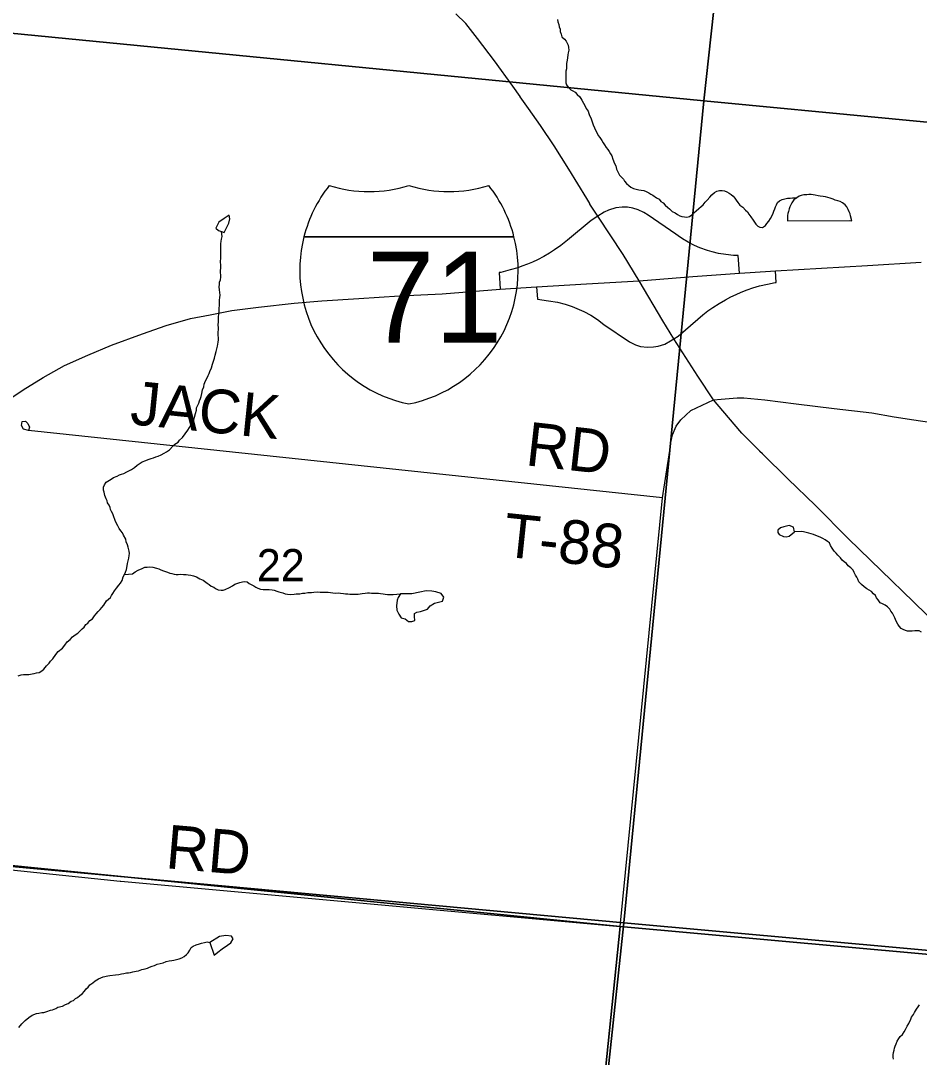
# Model space of a CAD drawing. Extents: x 0 to 1064, y 0 to 440.
# Drawn here: x 276.2 to 294.9, y 198.04 to 219.61 of the extents above; entities that cross this region are included whole.
import ezdxf

# ---------------------------------------------------------------- set-up
doc = ezdxf.new("R2010")
doc.units = 0
for name, color, linetype in [('GM_X_Interchange_Ramps', 7, 'Continuous'), ('GM_X_Interstate_Location', 7, 'Continuous'), ('GM_X_Interstate_Route', 7, 'Continuous'), ('GM_X_Interstate_Shield', 7, 'Continuous'), ('GM_X_Minor_Lake', 7, 'Continuous'), ('GM_X_Minor_River', 7, 'Continuous'), ('GM_X_Section', 7, 'Continuous'), ('GM_X_Section_Text', 7, 'Continuous'), ('GM_X_State_Route', 7, 'Continuous'), ('GM_X_Township', 7, 'Continuous'), ('GM_X_Township_Road', 7, 'Continuous'), ('GM_X_Township_Road_Text', 7, 'Continuous')]:
    doc.layers.add(name, color=color, linetype=linetype)

msp = doc.modelspace()

# ---------------------------------------------------------------- linework, layer by layer
at = {"layer": 'GM_X_Interchange_Ramps'}
for points in [[(291.163, 214.351), (291.137, 214.719), (291.036, 214.723), (290.875, 214.74), (290.728, 214.765), (290.593, 214.796), (290.496, 214.825), (290.338, 214.881), (290.222, 214.932), (290.094, 214.997), (289.979, 215.065), (289.884, 215.128), (289.835, 215.163), (289.263, 215.561), (289.171, 215.618), (289.055, 215.671), (288.939, 215.705), (288.83, 215.723), (288.721, 215.728), (288.59, 215.712), (288.433, 215.666), (288.342, 215.619), (288.214, 215.537)], [(288.214, 215.537), (288.077, 215.45), (287.582, 215.039), (287.446, 214.932), (287.311, 214.837), (287.21, 214.772), (287.088, 214.702), (286.955, 214.632), (286.853, 214.585), (286.752, 214.542), (286.632, 214.497), (286.545, 214.467), (286.387, 214.421), (286.197, 214.369), (286.16, 214.364), (286.183, 214.017)], [(289.792, 212.983), (289.883, 213.04), (290.295, 213.395), (290.399, 213.484), (290.505, 213.566), (290.61, 213.641), (290.739, 213.724), (290.871, 213.801), (290.981, 213.859), (291.09, 213.911), (291.196, 213.957), (291.322, 214.006), (291.44, 214.045), (291.579, 214.086), (291.745, 214.126), (291.904, 214.158), (291.925, 214.161), (291.91, 214.398)], [(286.939, 214.066), (286.956, 213.809), (287.188, 213.777), (287.377, 213.747), (287.533, 213.708), (287.676, 213.661), (287.92, 213.558), (288.065, 213.477), (288.204, 213.388), (288.341, 213.288), (288.87, 212.925), (288.997, 212.861), (289.101, 212.829), (289.247, 212.81), (289.371, 212.817), (289.467, 212.836), (289.608, 212.878), (289.729, 212.944), (289.792, 212.983)]]:
    msp.add_lwpolyline(points, dxfattribs=at)
at = {"layer": 'GM_X_Interstate_Route'}
msp.add_lwpolyline([(275.782, 211.603), (276.252, 211.926), (276.672, 212.184), (277.116, 212.429), (277.602, 212.649), (278.088, 212.856), (278.738, 213.09), (279.229, 213.261), (279.738, 213.407), (280.148, 213.489), (280.594, 213.576), (281.15, 213.642), (281.894, 213.728), (282.467, 213.776), (283.236, 213.825), (284.083, 213.878), (284.973, 213.924), (286.183, 214.017), (286.939, 214.066), (287.978, 214.128), (289.074, 214.193), (290.192, 214.283), (291.163, 214.351), (291.381, 214.364), (291.91, 214.398), (293.825, 214.514), (294.946, 214.579)], dxfattribs=at)
at = {"layer": 'GM_X_Interstate_Shield'}
for p, q in [((282.096, 215.11), (286.468, 215.11)), ((286.468, 215.11), (282.096, 215.11)), ((286.468, 215.11), (282.096, 215.11))]:
    msp.add_line(p, q, dxfattribs=at)
for centre, start, end in [((284.851, 214.414), 141.669, 165.8066), ((283.452, 218.893), 253.0091, 286.9909), ((285.113, 218.893), 253.0091, 286.9909), ((283.714, 214.414), 14.1934, 38.331), ((284.851, 214.414), 165.8066, 258.463), ((283.714, 214.414), 281.537, 14.1934)]:
    msp.add_arc(centre, 2.841, start, end, dxfattribs=at)
at = {"layer": 'GM_X_Minor_Lake'}
for points in [[(293.5, 215.445), (293.472, 215.543), (293.462, 215.585), (293.445, 215.628), (293.422, 215.678), (293.394, 215.733), (293.358, 215.777), (293.305, 215.815), (293.257, 215.841), (293.209, 215.86), (293.155, 215.874), (293.113, 215.894), (293.052, 215.914), (292.998, 215.928), (292.95, 215.941), (292.901, 215.949), (292.841, 215.957), (292.798, 215.964), (292.738, 215.978), (292.696, 215.986), (292.653, 215.987), (292.604, 215.988), (292.562, 215.984), (292.501, 215.985), (292.445, 215.969), (292.402, 215.952), (292.352, 215.917), (292.296, 215.876), (292.252, 215.817), (292.232, 215.775), (292.212, 215.733), (292.193, 215.691), (292.179, 215.637), (292.171, 215.595), (292.164, 215.553), (292.162, 215.498), (292.16, 215.443)], [(280.261, 215.29), (280.315, 215.241), (280.381, 215.221), (280.435, 215.201), (280.486, 215.297), (280.531, 215.393), (280.552, 215.484), (280.542, 215.563), (280.436, 215.493), (280.325, 215.411)], [(280.325, 215.411), (280.261, 215.29)], [(292.16, 215.443), (293.457, 215.446), (293.5, 215.445)], [(284.105, 207.68), (284.061, 207.602), (284.035, 207.547), (284.02, 207.432), (284.03, 207.341), (284.071, 207.255), (284.118, 207.181), (284.202, 207.16), (284.274, 207.104), (284.341, 207.102), (284.402, 207.125), (284.398, 207.21), (284.4, 207.271), (284.449, 207.3), (284.523, 207.311), (284.584, 207.333), (284.67, 207.362), (284.727, 207.433), (284.813, 207.486), (284.923, 207.514), (284.979, 207.531), (285.011, 207.609), (284.952, 207.69), (284.843, 207.723), (284.758, 207.737), (284.643, 207.746), (284.508, 207.718)], [(284.508, 207.718), (284.343, 207.68), (284.203, 207.677), (284.105, 207.68)], [(280.141, 200.428), (280.225, 200.158), (280.306, 200.223), (280.393, 200.294), (280.505, 200.371), (280.573, 200.418), (280.623, 200.502), (280.588, 200.557), (280.473, 200.572), (280.338, 200.551)], [(280.338, 200.551), (280.141, 200.428)]]:
    msp.add_lwpolyline(points, dxfattribs=at)
at = {"layer": 'GM_X_Minor_River'}
for points in [[(287.372, 219.629), (287.383, 219.58), (287.399, 219.525), (287.41, 219.482), (287.427, 219.433), (287.431, 219.384), (287.448, 219.329), (287.464, 219.274), (287.517, 219.224), (287.552, 219.18), (287.575, 219.137), (287.598, 219.094), (287.603, 219.051), (287.607, 218.99), (287.599, 218.936), (287.592, 218.894), (287.584, 218.833), (287.576, 218.785), (287.561, 218.713), (287.558, 218.603), (287.55, 218.555), (287.547, 218.47), (287.546, 218.428), (287.544, 218.373), (287.548, 218.312), (287.559, 218.269), (287.594, 218.226), (287.653, 218.169), (287.695, 218.15), (287.743, 218.118), (287.784, 218.074), (287.837, 218.024), (287.883, 217.95), (287.918, 217.888), (287.941, 217.845), (287.969, 217.777), (288.01, 217.721), (288.026, 217.678), (288.043, 217.635), (288.066, 217.586), (288.083, 217.543), (288.094, 217.5), (288.116, 217.439), (288.144, 217.377), (288.167, 217.328), (288.202, 217.266), (288.218, 217.217), (288.253, 217.173), (288.294, 217.111), (288.323, 217.068), (288.352, 217.024), (288.387, 216.969), (288.422, 216.925), (288.451, 216.882), (288.48, 216.838), (288.503, 216.795), (288.525, 216.728), (288.558, 216.636), (288.587, 216.586), (288.603, 216.519), (288.637, 216.451), (288.666, 216.395), (288.707, 216.352), (288.748, 216.308), (288.771, 216.265), (288.813, 216.221), (288.86, 216.177), (288.901, 216.145), (288.955, 216.113), (289.009, 216.099), (289.064, 216.086), (289.118, 216.078), (289.173, 216.07), (289.221, 216.05), (289.275, 216.024), (289.317, 215.999), (289.358, 215.973), (289.436, 215.922), (289.49, 215.89), (289.525, 215.847), (289.572, 215.815), (289.613, 215.765), (289.667, 215.721), (289.708, 215.689), (289.761, 215.639), (289.821, 215.607), (289.875, 215.575), (289.923, 215.549), (289.965, 215.53), (290.019, 215.522), (290.068, 215.52), (290.123, 215.531), (290.173, 215.566), (290.211, 215.607), (290.261, 215.648)], [(290.261, 215.648), (290.318, 215.701), (290.362, 215.742), (290.405, 215.777), (290.45, 215.83), (290.488, 215.872), (290.545, 215.937), (290.589, 215.984), (290.645, 216.031), (290.689, 216.06), (290.744, 216.07), (290.799, 216.074), (290.847, 216.067), (290.895, 216.047), (290.949, 216.021), (290.991, 215.99), (291.032, 215.958), (291.068, 215.914), (291.09, 215.871), (291.125, 215.822), (291.172, 215.765), (291.232, 215.727), (291.285, 215.665), (291.326, 215.627), (291.355, 215.578), (291.396, 215.522), (291.448, 215.459), (291.477, 215.416), (291.5, 215.373), (291.541, 215.329), (291.583, 215.31), (291.638, 215.302), (291.7, 215.342), (291.732, 215.384), (291.776, 215.437), (291.809, 215.491), (291.841, 215.55), (291.861, 215.598), (291.88, 215.64), (291.894, 215.695), (291.914, 215.736), (291.934, 215.778), (291.953, 215.82), (291.997, 215.855), (292.053, 215.884), (292.108, 215.9), (292.163, 215.911), (292.218, 215.915), (292.267, 215.92), (292.352, 215.917)], [(280.317, 213.223), (280.313, 213.272), (280.315, 213.344), (280.317, 213.399), (280.319, 213.454), (280.326, 213.496), (280.334, 213.568), (280.33, 213.623), (280.338, 213.678), (280.34, 213.738), (280.342, 213.793), (280.344, 213.847), (280.351, 213.896), (280.347, 213.951), (280.337, 214.005), (280.333, 214.066), (280.34, 214.115), (280.342, 214.169), (280.362, 214.217), (280.37, 214.272), (280.365, 214.32), (280.361, 214.363), (280.362, 214.411), (280.364, 214.46), (280.366, 214.509), (280.362, 214.594), (280.365, 214.666), (280.367, 214.739), (280.369, 214.8), (280.365, 214.855), (280.367, 214.909), (280.368, 214.964), (280.376, 215.018), (280.384, 215.061), (280.392, 215.115), (280.381, 215.221)], [(278.403, 208.188), (278.418, 208.26), (278.425, 208.309), (278.44, 208.369), (278.454, 208.423), (278.462, 208.478), (278.463, 208.52), (278.458, 208.569), (278.437, 208.648), (278.426, 208.697), (278.398, 208.765), (278.388, 208.82), (278.342, 208.9), (278.319, 208.949), (278.284, 208.993), (278.249, 209.043), (278.226, 209.098), (278.174, 209.185), (278.158, 209.228), (278.141, 209.283), (278.119, 209.344), (278.09, 209.394), (278.073, 209.437), (278.062, 209.48), (278.045, 209.523), (278.011, 209.572), (278, 209.615), (277.983, 209.658), (277.955, 209.726), (277.939, 209.793), (277.922, 209.836), (277.924, 209.897), (277.944, 209.951), (277.982, 210.004), (278.082, 210.068), (278.132, 210.103), (278.206, 210.131), (278.255, 210.154), (278.298, 210.17), (278.347, 210.181), (278.409, 210.216), (278.508, 210.267), (278.571, 210.308), (278.627, 210.355), (278.689, 210.401), (278.733, 210.43), (278.807, 210.452), (278.856, 210.475), (278.918, 210.497), (278.967, 210.508), (279.016, 210.531), (279.066, 210.547), (279.128, 210.576), (279.189, 210.604), (279.233, 210.633), (279.301, 210.68), (279.371, 210.751), (279.409, 210.792), (279.477, 210.838), (279.509, 210.88), (279.566, 210.933), (279.623, 211.01), (279.68, 211.087), (279.712, 211.141), (279.745, 211.2), (279.771, 211.242), (279.803, 211.296), (279.817, 211.356), (279.838, 211.434), (279.858, 211.501), (279.86, 211.549), (279.88, 211.591), (279.906, 211.651), (279.926, 211.699), (279.946, 211.747), (279.959, 211.789), (279.973, 211.849), (279.988, 211.928), (280.014, 211.988), (280.022, 212.042), (280.049, 212.114), (280.081, 212.174), (280.101, 212.222), (280.121, 212.263), (280.141, 212.305), (280.174, 212.383), (280.194, 212.456), (280.215, 212.522), (280.235, 212.582), (280.249, 212.648), (280.27, 212.72), (280.284, 212.781), (280.298, 212.835), (280.306, 212.877), (280.313, 212.919), (280.315, 212.968), (280.316, 213.01), (280.312, 213.065), (280.314, 213.126), (280.316, 213.18), (280.317, 213.223)], [(292.309, 208.969), (292.287, 209.067), (292.197, 209.105), (292.087, 209.077), (292.013, 209.055), (291.957, 209.002), (291.962, 208.959), (291.991, 208.916)], [(291.991, 208.916), (292.076, 208.871), (292.136, 208.864), (292.197, 208.88), (292.309, 208.969)], [(294.952, 206.881), (294.899, 206.913), (294.813, 206.91), (294.758, 206.906), (294.703, 206.901), (294.661, 206.903), (294.619, 206.916), (294.57, 206.936), (294.529, 206.961), (294.487, 207.005), (294.458, 207.048), (294.424, 207.11), (294.396, 207.178), (294.367, 207.233), (294.344, 207.277), (294.315, 207.32), (294.292, 207.363), (294.245, 207.413), (294.191, 207.445), (294.138, 207.471), (294.09, 207.491), (294.049, 207.553), (294.014, 207.596), (293.991, 207.646), (293.95, 207.683), (293.909, 207.727), (293.861, 207.759), (293.813, 207.785), (293.759, 207.823), (293.7, 207.873), (293.647, 207.93), (293.625, 207.985), (293.602, 208.028), (293.573, 208.072), (293.55, 208.127), (293.527, 208.17), (293.48, 208.22), (293.421, 208.264), (293.386, 208.308), (293.338, 208.346), (293.297, 208.384), (293.262, 208.427), (293.209, 208.483), (293.174, 208.527), (293.132, 208.565), (293.092, 208.627), (293.057, 208.689), (293.035, 208.738), (292.993, 208.769), (292.945, 208.801), (292.898, 208.833), (292.856, 208.853), (292.808, 208.872), (292.754, 208.892), (292.7, 208.918), (292.657, 208.932), (292.603, 208.945), (292.549, 208.959), (292.494, 208.967), (292.452, 208.974), (292.309, 208.969)], [(276.15, 205.975), (276.212, 205.997), (276.261, 206.002), (276.303, 206), (276.371, 206.004), (276.438, 206.014), (276.481, 206.025), (276.53, 206.036), (276.585, 206.046), (276.641, 206.075), (276.685, 206.116), (276.736, 206.181), (276.792, 206.234), (276.824, 206.282), (276.868, 206.329), (276.932, 206.418), (276.983, 206.483), (277.071, 206.553), (277.121, 206.612), (277.172, 206.684), (277.229, 206.731), (277.279, 206.784), (277.335, 206.824), (277.391, 206.865), (277.435, 206.906), (277.48, 206.954), (277.523, 206.989), (277.556, 207.042), (277.599, 207.071), (277.637, 207.125), (277.693, 207.159), (277.738, 207.225), (277.77, 207.266), (277.814, 207.314), (277.858, 207.355), (277.89, 207.396), (277.934, 207.443), (277.986, 207.533), (278.067, 207.603), (278.093, 207.645), (278.119, 207.687), (278.151, 207.746), (278.196, 207.8), (278.246, 207.859), (278.278, 207.9), (278.31, 207.96), (278.337, 208.032), (278.363, 208.08), (278.383, 208.134), (278.403, 208.188)], [(278.363, 208.08), (278.528, 208.093), (278.584, 208.14), (278.646, 208.174), (278.727, 208.208), (278.782, 208.237), (278.837, 208.235), (278.886, 208.24), (278.953, 208.232), (279.025, 208.217), (279.079, 208.197), (279.121, 208.178), (279.176, 208.158), (279.218, 208.145), (279.26, 208.131), (279.302, 208.112), (279.344, 208.104), (279.393, 208.091), (279.435, 208.083), (279.477, 208.082), (279.532, 208.086), (279.593, 208.084), (279.642, 208.083), (279.684, 208.075), (279.739, 208.068), (279.799, 208.054), (279.859, 208.034), (279.931, 207.995), (279.997, 207.963), (280.081, 207.905), (280.122, 207.874), (280.164, 207.842), (280.218, 207.816), (280.259, 207.791), (280.313, 207.765), (280.374, 207.757), (280.417, 207.755), (280.46, 207.772), (280.546, 207.812), (280.608, 207.847), (280.658, 207.881), (280.701, 207.892), (280.763, 207.915), (280.818, 207.931), (280.867, 207.936), (280.915, 207.928), (280.957, 207.897), (280.999, 207.877), (281.053, 207.845), (281.095, 207.819), (281.137, 207.8), (281.191, 207.78), (281.245, 207.772), (281.312, 207.77), (281.373, 207.768), (281.434, 207.766), (281.476, 207.759), (281.53, 207.739), (281.572, 207.72), (281.657, 207.699), (281.705, 207.679), (281.753, 207.672), (281.808, 207.664), (281.893, 207.673), (281.936, 207.678), (282.009, 207.682), (282.065, 207.692), (282.113, 207.697), (282.181, 207.707), (282.254, 207.711), (282.303, 207.715), (282.388, 207.719), (282.431, 207.717), (282.479, 207.716), (282.528, 207.714), (282.601, 207.712), (282.65, 207.711), (282.698, 207.703), (282.753, 207.695), (282.808, 207.7), (282.856, 207.692), (282.923, 207.69), (282.965, 207.683), (283.008, 207.681), (283.05, 207.674), (283.105, 207.672), (283.166, 207.67), (283.227, 207.675), (283.306, 207.684), (283.368, 207.695), (283.417, 207.699), (283.459, 207.698), (283.502, 207.697), (283.55, 207.695), (283.599, 207.694), (283.648, 207.692)], [(283.648, 207.692), (283.69, 207.685), (283.745, 207.683), (283.787, 207.676), (283.836, 207.668), (283.896, 207.666), (283.951, 207.664), (284.105, 207.68)], [(276.164, 198.658), (276.228, 198.735), (276.297, 198.8), (276.372, 198.864), (276.441, 198.911), (276.533, 198.944), (276.582, 198.955), (276.643, 198.965), (276.686, 198.97), (276.748, 198.986), (276.822, 199.014), (276.865, 199.025), (276.932, 199.053), (276.976, 199.076), (277.068, 199.098), (277.136, 199.132), (277.192, 199.155), (277.254, 199.201), (277.297, 199.218), (277.341, 199.259), (277.385, 199.282), (277.435, 199.323), (277.478, 199.358), (277.529, 199.411), (277.561, 199.459), (277.605, 199.494), (277.637, 199.542), (277.705, 199.588), (277.749, 199.629), (277.824, 199.669), (277.916, 199.709), (278.014, 199.73), (278.057, 199.741), (278.173, 199.75), (278.241, 199.76), (278.302, 199.77), (278.351, 199.781), (278.4, 199.791), (278.443, 199.796), (278.485, 199.801), (278.535, 199.811), (278.602, 199.828), (278.651, 199.838), (278.725, 199.86), (278.792, 199.876), (278.842, 199.893), (278.885, 199.91), (278.94, 199.932), (278.983, 199.943), (279.039, 199.972), (279.101, 199.988), (279.168, 200.004), (279.23, 200.027), (279.291, 200.043), (279.346, 200.053), (279.389, 200.058), (279.444, 200.069), (279.5, 200.085), (279.555, 200.108), (279.605, 200.137), (279.649, 200.172), (279.686, 200.213), (279.725, 200.266), (279.751, 200.32), (279.794, 200.349), (279.856, 200.378), (279.924, 200.4), (279.967, 200.411), (280.028, 200.427), (280.084, 200.437), (280.141, 200.428)], [(294.367, 197.999), (294.362, 198.042), (294.363, 198.084), (294.365, 198.139), (294.379, 198.181), (294.386, 198.223), (294.4, 198.265), (294.42, 198.319), (294.446, 198.373), (294.478, 198.427), (294.504, 198.468), (294.554, 198.509), (294.586, 198.563), (294.618, 198.616), (294.651, 198.682), (294.683, 198.742), (294.729, 198.832), (294.743, 198.874), (294.787, 198.927), (294.807, 198.969), (294.845, 199.041), (294.884, 199.088), (294.909, 199.13)]]:
    msp.add_lwpolyline(points, dxfattribs=at)
at = {"layer": 'GM_X_Section'}
for points in [[(292.003, 232.393), (290.417, 217.941), (274.783, 219.463), (276.183, 234.07)], [(292.003, 232.393), (307.602, 230.968), (306.101, 216.441), (290.417, 217.941)], [(274.783, 219.463), (290.417, 217.941), (288.758, 200.836), (273.219, 202.266)], [(290.417, 217.941), (306.101, 216.441), (304.455, 199.415), (288.758, 200.836)], [(288.758, 200.836), (287.113, 185.421), (271.692, 187.055), (273.219, 202.266)], [(288.758, 200.836), (304.455, 199.415), (302.913, 183.69), (287.113, 185.421)]]:
    msp.add_lwpolyline(points, close=True, dxfattribs=at)
at = {"layer": 'GM_X_State_Route'}
for points in [[(286.598, 218.025), (286.596, 218.027), (286.447, 218.242), (286.063, 218.768), (285.712, 219.238), (285.467, 219.551), (285.26, 219.748)], [(288.044, 215.8), (287.985, 215.904), (287.607, 216.517), (287.302, 217.001), (287.017, 217.429), (286.77, 217.776), (286.598, 218.025)], [(290.619, 211.72), (290.292, 212.208), (289.792, 212.983), (289.568, 213.362), (289.074, 214.193), (288.738, 214.738), (288.214, 215.537), (288.049, 215.792), (288.044, 215.8)], [(290.619, 211.72), (290.783, 211.728), (291.111, 211.76), (291.254, 211.758), (291.69, 211.716), (292.342, 211.636), (293.134, 211.539), (293.914, 211.448), (294.384, 211.365), (294.79, 211.3), (295.446, 211.206)], [(291.588, 210.642), (291.583, 210.647), (291.211, 211.025), (290.931, 211.346), (290.619, 211.72)], [(295.347, 206.966), (294.783, 207.517), (294.11, 208.169), (293.434, 208.826), (292.746, 209.518), (292.169, 210.073), (291.639, 210.59), (291.588, 210.642)]]:
    msp.add_lwpolyline(points, dxfattribs=at)
at = {"layer": 'GM_X_Township'}
for points in [[(304.391, 199.334), (288.677, 200.756), (267.411, 202.889), (267.34, 202.897), (266.393, 202.989), (264.989, 203.143), (264.791, 203.165), (255.435, 204.058), (244.159, 205.157), (243.767, 205.195), (241.859, 205.381), (240.993, 205.465), (240.893, 205.475), (240.481, 205.515), (234.109, 206.137), (211.953, 208.299), (208.261, 208.659), (208.143, 208.67), (191.843, 210.26)], [(191.843, 210.26), (208.143, 208.67), (208.261, 208.659), (211.953, 208.299), (234.109, 206.137), (240.481, 205.515), (240.893, 205.475), (240.993, 205.465), (241.859, 205.381), (243.767, 205.195), (244.159, 205.157), (255.435, 204.058), (264.791, 203.165), (264.989, 203.143), (266.393, 202.989), (267.34, 202.897), (267.411, 202.889), (288.677, 200.756), (287.73, 191.491)], [(287.73, 191.491), (288.677, 200.756), (304.391, 199.334)]]:
    msp.add_lwpolyline(points, dxfattribs=at)
at = {"layer": 'GM_X_Township_Road'}
for points in [[(289.709, 210.663), (289.734, 210.826), (289.77, 210.986), (289.846, 211.167), (289.942, 211.303), (290.15, 211.498), (290.619, 211.72)], [(289.559, 209.678), (276.362, 211.076), (276.261, 211.11), (276.221, 211.186), (276.234, 211.264), (276.298, 211.27), (276.352, 211.225), (276.384, 211.145), (276.362, 211.079)], [(288.677, 200.756), (288.677, 200.756), (289.559, 209.678), (289.709, 210.663)], [(267.784, 202.355), (268.033, 202.465), (268.473, 202.595), (268.772, 202.652), (269.058, 202.66), (278.273, 201.702), (278.283, 201.702)], [(278.283, 201.702), (288.677, 200.756)], [(287.59, 191.397), (287.628, 191.423), (287.73, 191.491), (288.677, 200.756)]]:
    msp.add_lwpolyline(points, dxfattribs=at)

# ---------------------------------------------------------------- texts
at = {"layer": 'GM_X_Interstate_Location'}
for s in ['-', '.', ',']:
    msp.add_text(s, height=0.00303, dxfattribs=at).set_placement((284.282, 213.902))
msp.add_text('71', height=0.00303, rotation=0, dxfattribs=at).set_placement((283.663, 213.274))
at = {"layer": 'GM_X_Interstate_Shield'}
msp.add_text('71', height=1.8939, dxfattribs=at).set_placement((283.407, 212.909))
at = {"layer": 'GM_X_Section_Text'}
msp.add_text('22', height=0.6697, rotation=0, dxfattribs=at).set_placement((281.116, 207.942))
at = {"layer": 'GM_X_Township_Road_Text'}
for s, rotation, p in [('JACK', 354.2073, (278.459, 211.212)), ('RD', 353.6054, (286.689, 210.358)), ('T-88', 353.973, (286.217, 208.461)), ('RD', 355.0719, (279.2, 201.973))]:
    msp.add_text(s, height=0.9091, rotation=rotation, dxfattribs=at).set_placement(p)

doc.saveas('drawing.dxf')
